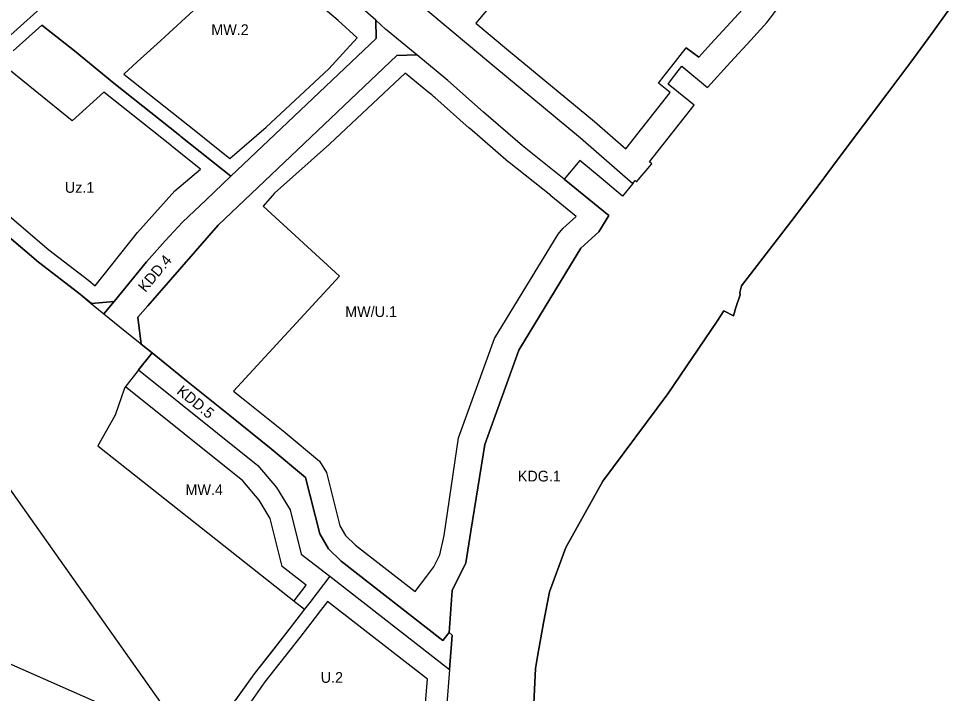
# Model space of a CAD drawing. Extents: x 7432050 to 7433361, y 5551438 to 5552391.
# Drawn here: x 7432993.3 to 7433340.6, y 5551703.3 to 5551955.2 of the extents above; entities that cross this region are included whole.
import ezdxf

# ---------------------------------------------------------------- set-up
doc = ezdxf.new("R2010")
doc.units = 0
for name, color, linetype in [('granica planu', 7, 'Continuous'), ('linie rozgraniczające', 7, 'Continuous'), ('MPZP_Niebyla_Na_Wzgorzach', 7, 'Continuous'), ('nieprzekraczalne linie zabudowy', 7, 'Continuous'), ('obowiązujące linie zabudowy', 7, 'Continuous'), ('oznaczenia przeznaczen', 7, 'Continuous')]:
    doc.layers.add(name, color=color, linetype=linetype)

msp = doc.modelspace()

# ---------------------------------------------------------------- linework, layer by layer
at = {"layer": 'granica planu'}
msp.add_lwpolyline([(7433340.63, 5551958.89), (7433334.03, 5551949.65), (7433327.25, 5551940.34), (7433325.81, 5551938.43), (7433317.28, 5551927.04), (7433299.87, 5551903.83), (7433291.7, 5551892.76), (7433281.49, 5551879.35), (7433263.07, 5551855.45), (7433262.42, 5551852.9), (7433262.54, 5551852.12), (7433260.89, 5551847.29), (7433260.05, 5551844.2), (7433256.47, 5551846.08), (7433253.97, 5551842.28), (7433235.62, 5551815.11), (7433211.26, 5551782.5), (7433197.51, 5551757.78), (7433191.44, 5551741.19), (7433189.14, 5551729.59), (7433186.94, 5551717.01), (7433186.18, 5551712.56), (7433185.05, 5551688.87)], dxfattribs=at)
at = {"layer": 'linie rozgraniczające'}
for p, q in [((7433126.53, 5551954.57), (7433118.67, 5551961.52)), ((7433334.03, 5551949.65), (7433340.63, 5551958.89)), ((7433126.65, 5551947.82), (7433126.53, 5551954.57)), ((7433130.36, 5551951.18), (7433126.53, 5551954.57)), ((7433126.53, 5551954.57), (7433126.65, 5551947.82)), ((7433001.88, 5551952.8), (7432991.21, 5551943.19)), ((7432991.21, 5551943.19), (7433001.88, 5551952.8)), ((7433014.08, 5551943.13), (7433001.88, 5551952.8)), ((7433001.88, 5551952.8), (7433014.08, 5551943.13)), ((7433130.84, 5551950.76), (7433130.36, 5551951.18)), ((7433139.85, 5551943.35), (7433130.84, 5551950.76)), ((7433072.44, 5551896.32), (7433126.65, 5551947.82)), ((7433126.65, 5551947.82), (7433072.44, 5551896.32)), ((7433327.25, 5551940.34), (7433334.03, 5551949.65)), ((7433028.82, 5551931.09), (7433014.08, 5551943.13)), ((7433014.08, 5551943.13), (7433028.82, 5551931.09)), ((7433134.4, 5551941.39), (7433067.69, 5551878.02)), ((7433067.69, 5551878.02), (7433134.4, 5551941.39)), ((7433141.87, 5551941.69), (7433134.4, 5551941.39)), ((7433134.4, 5551941.39), (7433141.87, 5551941.69)), ((7433141.87, 5551941.69), (7433139.85, 5551943.35)), ((7433153.5, 5551932.08), (7433141.87, 5551941.69)), ((7433325.81, 5551938.43), (7433327.25, 5551940.34)), ((7433053.38, 5551911.61), (7433028.82, 5551931.09)), ((7433028.82, 5551931.09), (7433053.38, 5551911.61)), ((7433166.76, 5551920.3), (7433153.5, 5551932.08)), ((7433181.38, 5551907.68), (7433166.76, 5551920.3)), ((7433053.85, 5551911.24), (7433053.38, 5551911.61)), ((7433053.38, 5551911.61), (7433053.85, 5551911.24)), ((7433072.44, 5551896.32), (7433053.85, 5551911.24)), ((7433053.85, 5551911.24), (7433072.44, 5551896.32)), ((7433196.92, 5551895.3), (7433181.38, 5551907.68)), ((7433291.7, 5551892.76), (7433299.87, 5551903.83)), ((7433063.24, 5551887.58), (7433072.44, 5551896.32)), ((7433072.44, 5551896.32), (7433063.24, 5551887.58)), ((7433281.49, 5551879.35), (7433291.7, 5551892.76)), ((7433054.39, 5551879.18), (7433063.24, 5551887.58)), ((7433063.24, 5551887.58), (7433054.39, 5551879.18)), ((7432977.09, 5551884.32), (7433000.73, 5551864.23)), ((7433000.73, 5551864.23), (7432977.09, 5551884.32)), ((7433067.69, 5551878.02), (7433041.44, 5551848.02)), ((7433041.44, 5551848.02), (7433067.69, 5551878.02)), ((7433047.95, 5551872.25), (7433054.39, 5551879.18)), ((7433054.39, 5551879.18), (7433047.95, 5551872.25)), ((7433041, 5551864.43), (7433047.95, 5551872.25)), ((7433047.95, 5551872.25), (7433041, 5551864.43)), ((7433028.89, 5551849.63), (7433041, 5551864.43)), ((7433262.54, 5551852.12), (7433262.42, 5551852.9)), ((7433025.09, 5551844.99), (7433028.89, 5551849.63)), ((7433043.07, 5551830.37), (7433038.07, 5551824.02)), ((7433038.07, 5551824.02), (7433043.07, 5551830.37)), ((7433038.07, 5551824.02), (7433082.54, 5551788.38)), ((7433038.07, 5551824.02), (7433038.07, 5551824.02)), ((7433211.26, 5551782.5), (7433235.62, 5551815.11)), ((7433082.54, 5551788.38), (7433089.55, 5551780.1)), ((7433105.64, 5551762.82), (7433100.4, 5551783.82)), ((7433100.4, 5551783.82), (7433105.64, 5551762.82)), ((7433089.55, 5551780.1), (7433094.65, 5551771.74)), ((7433094.65, 5551771.74), (7433098.76, 5551755.3)), ((7433098.76, 5551755.3), (7433109.42, 5551747)), ((7433109.42, 5551747), (7433154.12, 5551712.23)), ((7433026.86, 5551698), (7432950.78, 5551731.59)), ((7433155.04, 5551725.04), (7433153.93, 5551725.95)), ((7433154.12, 5551712.23), (7433155.04, 5551725.04)), ((7433154.12, 5551712.23), (7433153.02, 5551697.71))]:
    msp.add_line(p, q, dxfattribs=at)
for points in [[(7433222.45, 5551893.65), (7433223.31, 5551894.75), (7433223.82, 5551894.31), (7433229.58, 5551901), (7433228.77, 5551901.72), (7433245.37, 5551922.89), (7433243.45, 5551924.46), (7433235.68, 5551930.76), (7433236.59, 5551931.93), (7433239.47, 5551935.66), (7433240.84, 5551937.43), (7433250.31, 5551929.49), (7433258.99, 5551938.96), (7433266.49, 5551947.13), (7433272.51, 5551953.7), (7433273.85, 5551955.48), (7433276.05, 5551958.41), (7433279.99, 5551963.18), (7433288.84, 5551975.06), (7433293.41, 5551981.61), (7433321.52, 5552019.16)], [(7433118.04, 5551981.58), (7433171.02, 5551937.14), (7433202.95, 5551910.71), (7433222.45, 5551893.65)], [(7433340.63, 5551958.89), (7433334.03, 5551949.65), (7433327.25, 5551940.34), (7433325.81, 5551938.43), (7433317.28, 5551927.04), (7433299.87, 5551903.83), (7433291.7, 5551892.76), (7433281.49, 5551879.35), (7433263.07, 5551855.45), (7433262.42, 5551852.9), (7433262.54, 5551852.12), (7433260.89, 5551847.29), (7433260.05, 5551844.2), (7433256.47, 5551846.08), (7433253.97, 5551842.28), (7433235.62, 5551815.11), (7433211.26, 5551782.5), (7433197.51, 5551757.78), (7433191.44, 5551741.19), (7433189.14, 5551729.59), (7433186.94, 5551717.01), (7433186.18, 5551712.56), (7433185.05, 5551688.87)], [(7433299.87, 5551903.83), (7433317.28, 5551927.04), (7433325.81, 5551938.43)], [(7433222.45, 5551893.65), (7433218.68, 5551888.85), (7433210.66, 5551895.68), (7433202.67, 5551902.18), (7433196.92, 5551895.3), (7433213.48, 5551881.68), (7433209.83, 5551875.6), (7433203.15, 5551869.5), (7433179.99, 5551831.43), (7433167.21, 5551796.2), (7433162.02, 5551763.83), (7433160.12, 5551751.97), (7433155.06, 5551741.67), (7433153.93, 5551725.95), (7433155.04, 5551725.04), (7433154.12, 5551712.23)], [(7433153.93, 5551725.95), (7433155.06, 5551741.67), (7433160.12, 5551751.97), (7433162.02, 5551763.83), (7433167.21, 5551796.2), (7433179.99, 5551831.43), (7433203.15, 5551869.5), (7433209.83, 5551875.6), (7433213.48, 5551881.68), (7433196.92, 5551895.3)], [(7433262.42, 5551852.9), (7433263.07, 5551855.45), (7433281.49, 5551879.35)], [(7433000.73, 5551864.23), (7433015.69, 5551852.7), (7433020.43, 5551848.78), (7433028.89, 5551849.63)], [(7433028.89, 5551849.63), (7433020.43, 5551848.78), (7433015.69, 5551852.7), (7433000.73, 5551864.23)], [(7433041, 5551864.43), (7433028.89, 5551849.63), (7433025.09, 5551844.99)], [(7433260.05, 5551844.2), (7433260.89, 5551847.29), (7433262.54, 5551852.12)], [(7433041.44, 5551848.02), (7433037.71, 5551843.75), (7433039.02, 5551833.66), (7433043.07, 5551830.37)], [(7433043.07, 5551830.37), (7433039.02, 5551833.66), (7433037.71, 5551843.75), (7433041.44, 5551848.02)], [(7433235.62, 5551815.11), (7433253.97, 5551842.28), (7433256.47, 5551846.08), (7433260.05, 5551844.2)], [(7433100.4, 5551783.82), (7433087.57, 5551794.6), (7433072.05, 5551807.03), (7433056.53, 5551819.47), (7433043.07, 5551830.37)], [(7433043.07, 5551830.37), (7433056.53, 5551819.47), (7433072.05, 5551807.03), (7433087.57, 5551794.6), (7433100.4, 5551783.82)], [(7433189.14, 5551729.59), (7433191.44, 5551741.19), (7433197.51, 5551757.78), (7433211.26, 5551782.5)], [(7433113.65, 5551752.58), (7433108.92, 5551757.27), (7433105.64, 5551762.82)], [(7433105.64, 5551762.82), (7433108.92, 5551757.27), (7433113.65, 5551752.58)], [(7433153.93, 5551725.95), (7433151.65, 5551723.02), (7433113.65, 5551752.58)], [(7433113.65, 5551752.58), (7433151.65, 5551723.02), (7433153.93, 5551725.95)], [(7433109.42, 5551747), (7433102, 5551737.25), (7433100.01, 5551734.68), (7433097.15, 5551730.96), (7433087.75, 5551718.9), (7433081.21, 5551710.55), (7433074.38, 5551701.03)], [(7433186.18, 5551712.56), (7433186.94, 5551717.01), (7433189.14, 5551729.59)], [(7433190.16, 5551592.1), (7433188.47, 5551631.14), (7433185.05, 5551688.87), (7433186.18, 5551712.56)]]:
    msp.add_lwpolyline(points, dxfattribs=at)
at = {"layer": 'MPZP_Niebyla_Na_Wzgorzach'}
msp.add_lwpolyline([(7432977.09, 5551884.32), (7433000.73, 5551864.23), (7433015.69, 5551852.7), (7433021.07, 5551848.25), (7433033.09, 5551838.49), (7433033.6, 5551838.07), (7433043.07, 5551830.37), (7433042.68, 5551829.88), (7433032.93, 5551817.5), (7433032.85, 5551817.27), (7433029.29, 5551807.1), (7433022.82, 5551795.73), (7433097.26, 5551736.86), (7433100.01, 5551734.68), (7433094.28, 5551727.25), (7433081.21, 5551710.55), (7433067.54, 5551691.5), (7433076.44, 5551677.23), (7433071.53, 5551670.11), (7433070.5, 5551665.12), (7433057.06, 5551684.66), (7433042.84, 5551690.94), (7433049.29, 5551695.66), (7432912.36, 5551889.43)], dxfattribs=at)
at = {"layer": 'nieprzekraczalne linie zabudowy'}
for p, q in [((7433163.91, 5551953.54), (7433163.91, 5551953.54)), ((7433163.91, 5551953.54), (7433176.14, 5551943.29)), ((7433109.01, 5551936.45), (7433119.6, 5551947.99)), ((7433247.1, 5551940.79), (7433242.38, 5551944.32)), ((7433242.38, 5551944.32), (7433247.1, 5551940.79)), ((7433013.3, 5551917.06), (7432990.3, 5551935.65)), ((7433145.99, 5551927.9), (7433137.59, 5551934.85)), ((7433232.12, 5551931.07), (7433234.22, 5551933.77)), ((7433236.37, 5551927.62), (7433232.12, 5551931.07)), ((7433025.06, 5551927.69), (7433013.3, 5551917.06)), ((7433147.47, 5551926.69), (7433145.99, 5551927.9)), ((7433148.29, 5551926), (7433147.47, 5551926.69)), ((7433219.85, 5551906.55), (7433236.37, 5551927.62)), ((7433073.53, 5551816.1), (7433073.53, 5551816.1)), ((7433073.53, 5551816.1), (7433077.05, 5551813.27)), ((7433077.05, 5551813.27), (7433092.57, 5551800.84)), ((7433118.94, 5551758.6), (7433141.24, 5551741.26)), ((7433141.24, 5551741.26), (7433145.57, 5551746.98))]:
    msp.add_line(p, q, dxfattribs=at)
for points in [[(7433247.1, 5551940.79), (7433251.62, 5551945.72), (7433259.12, 5551953.89), (7433264.81, 5551960.1), (7433265.86, 5551961.49), (7433268.19, 5551964.6), (7433272.12, 5551969.35), (7433274.47, 5551972.51), (7433280.88, 5551981.13), (7433285.3, 5551987.47), (7433313.56, 5552025.22)], [(7433082.37, 5551980.01), (7433079.34, 5551977.24), (7433069.39, 5551968.13), (7433060.16, 5551959.7), (7433050.94, 5551951.27), (7433049.42, 5551949.89), (7433046.18, 5551946.93), (7433037.5, 5551939.01), (7433032.56, 5551934.5)], [(7433119.6, 5551947.99), (7433112.56, 5551954.45), (7433082.37, 5551980.01)], [(7432951.82, 5551914.45), (7432959.08, 5551920.99), (7432973.55, 5551934.02), (7432987.86, 5551946.91), (7433012.27, 5551968.89)], [(7433234.22, 5551933.77), (7433237.1, 5551937.5), (7433242.38, 5551944.32)], [(7433176.14, 5551943.29), (7433208.14, 5551916.8), (7433219.85, 5551906.55)], [(7433032.56, 5551934.5), (7433056.47, 5551915.54), (7433056.95, 5551915.16), (7433072.14, 5551902.98)], [(7433072.14, 5551902.98), (7433085.69, 5551914.65), (7433109.01, 5551936.45)], [(7433061.2, 5551898.93), (7433050.75, 5551907.32), (7433050.28, 5551907.68), (7433025.06, 5551927.69)], [(7433161.53, 5551914.24), (7433161.45, 5551914.32), (7433148.6, 5551925.73), (7433148.29, 5551926)], [(7433176.4, 5551901.42), (7433176.15, 5551901.62), (7433161.53, 5551914.24)], [(7432959.34, 5551907.77), (7432966.87, 5551901.06), (7432980.99, 5551888.87), (7433004.5, 5551868.9), (7433019.43, 5551857.39), (7433021.81, 5551855.43)], [(7433021.81, 5551855.43), (7433037.61, 5551875.28), (7433051.58, 5551890.84), (7433061.2, 5551898.93)], [(7433191.89, 5551889.08), (7433191.84, 5551889.12), (7433176.4, 5551901.42)], [(7433201.29, 5551881.35), (7433191.93, 5551889.04), (7433191.89, 5551889.08)], [(7433194.61, 5551874.7), (7433196.41, 5551876.88), (7433201.29, 5551881.35)], [(7433152.05, 5551762.2), (7433157.49, 5551798.72), (7433170.93, 5551835.78), (7433194.61, 5551874.7)], [(7433100.65, 5551743.69), (7433091.67, 5551750.68), (7433087.19, 5551768.62), (7433083.04, 5551775.4), (7433076.93, 5551782.62), (7433033.12, 5551817.74)], [(7433092.57, 5551800.84), (7433092.72, 5551800.72), (7433105.55, 5551789.94)], [(7433105.55, 5551789.94), (7433108.16, 5551785.76), (7433113.12, 5551765.89)], [(7433113.12, 5551765.89), (7433115.28, 5551762.23), (7433118.94, 5551758.6)], [(7433145.57, 5551746.98), (7433148.28, 5551750.54), (7433150.48, 5551755.03), (7433152.05, 5551762.2)], [(7433096.1, 5551737.78), (7433100.65, 5551743.69)], [(7433108.52, 5551737.56), (7433105.97, 5551734.21), (7433103.97, 5551731.62), (7433098.23, 5551724.18), (7433085.21, 5551707.55), (7433079.01, 5551698.91)], [(7433140.07, 5551637.71), (7433141.84, 5551645.79), (7433143.54, 5551665.89), (7433143.72, 5551671.24), (7433144.16, 5551680.69), (7433144.04, 5551680.79), (7433145.04, 5551698.24), (7433145.82, 5551708.55), (7433108.52, 5551737.56)]]:
    msp.add_lwpolyline(points, dxfattribs=at)
at = {"layer": 'obowiązujące linie zabudowy'}
for p, q in [((7433183.61, 5551977.02), (7433163.91, 5551953.54)), ((7433137.59, 5551934.85), (7433109.47, 5551908.5)), ((7433137.59, 5551934.85), (7433137.59, 5551934.85)), ((7433088.83, 5551890.02), (7433084.58, 5551885.16)), ((7433084.58, 5551885.16), (7433112.99, 5551859.05)), ((7433112.99, 5551859.05), (7433073.53, 5551816.1))]:
    msp.add_line(p, q, dxfattribs=at)
msp.add_lwpolyline([(7433109.47, 5551908.5), (7433109.33, 5551908.38), (7433088.83, 5551890.02)], dxfattribs=at)

# ---------------------------------------------------------------- texts
at = {"layer": 'oznaczenia przeznaczen'}
for s, p in [('MW.2', (7433065.19, 5551949.07)), ('Uz.1', (7433010.54, 5551890.16)), ('MW/U.1', (7433115.16, 5551843.79)), ('KDG.1', (7433179.58, 5551782.39)), ('MW.4', (7433055.55, 5551777.3)), ('U.2', (7433106.02, 5551707.22))]:
    msp.add_text(s, height=4, dxfattribs=at).set_placement(p)
for s, rotation, p in [('KDD.4', 49.9979, (7433040.58, 5551852.77)), ('KDD.5', 320.8983, (7433051.97, 5551815.49))]:
    msp.add_text(s, height=4, rotation=rotation, dxfattribs=at).set_placement(p)

doc.saveas('drawing.dxf')
